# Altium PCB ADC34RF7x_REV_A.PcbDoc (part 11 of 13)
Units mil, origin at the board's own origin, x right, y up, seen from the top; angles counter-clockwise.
Board outline 6250 x 2716.54 mil, 18 copper layers (Top Layer, L2 GND, L3 PWR, L4 GND, L5 PWR/SIG, L6 GND, L7 SIGNAL, L8 GND, L9 GND, L10 SIGNAL, L11 GND, L12 SIGNAL, L13 GND, L14 PWR, L15 GND, L16 PWR/SIG, L16 GND, Bottom Layer), stack 95.314 mil thick; 668 components, 786 nets, 3150 pads, 2020 vias.
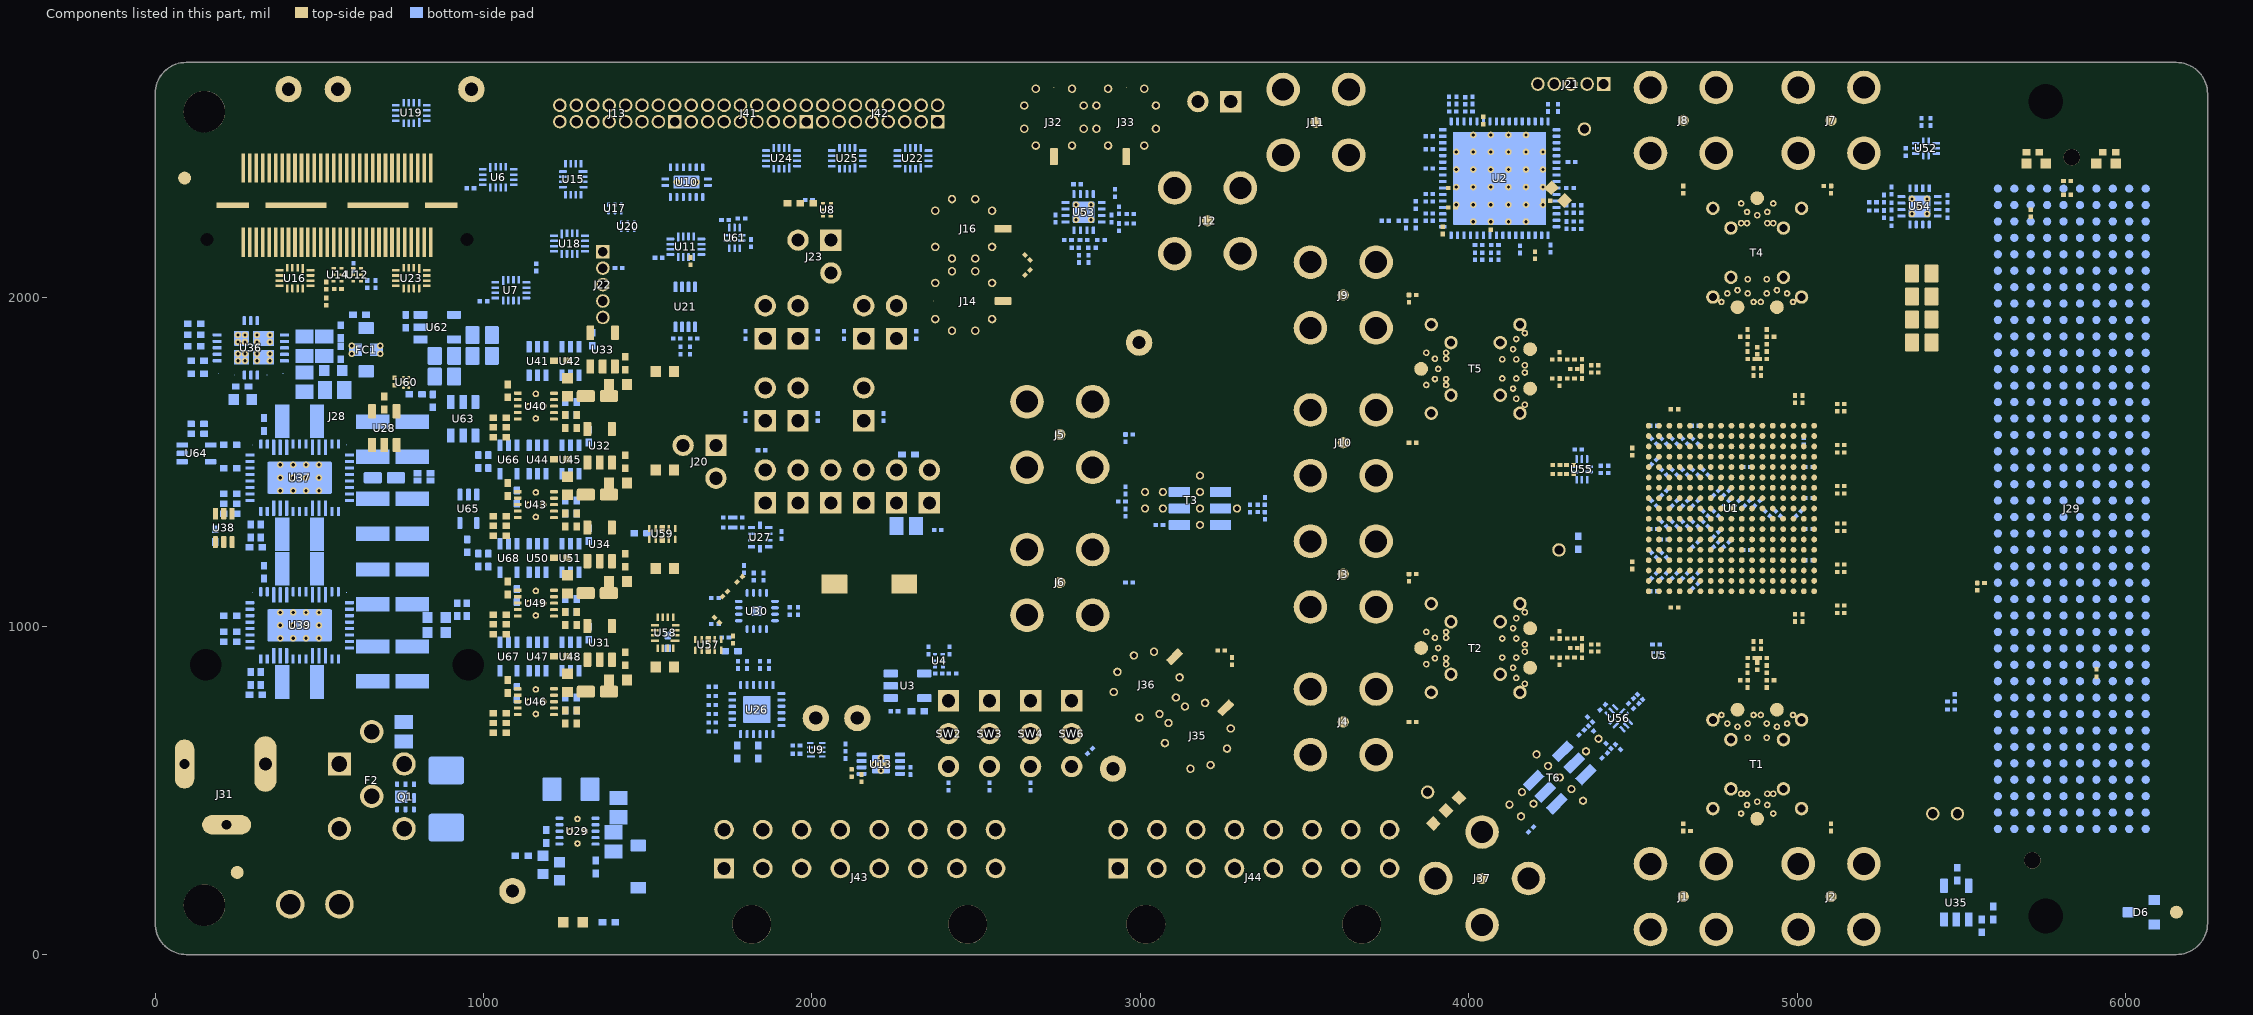
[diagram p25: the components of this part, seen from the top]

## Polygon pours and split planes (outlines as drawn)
GND on L7 SIGNAL "L2_GND" (solid, remove dead copper, pour order 106): 0,2716.54 0,0 6250,0 6250,2716.54
3p3V_Utility on L7 SIGNAL "L7_3p3V_Utility" (solid, remove dead copper, pour order 61): 4685.56,224.22 5983.78,224.22 6054.93,153.07 6054.93,11.36 6169.15,11.36 6169.15,623.31 5056.51,623.31 4713.3,966.52 4113.91,966.52 4113.91,1358.27 4366.11,1358.27 4366.11,1570.02 3974.52,1570.02 3974.52,939.64 2424.45,939.64 2424.45,1416.58 1599.5,1416.58 1599.5,1625.36 2405,1625.36 2405,2122.59 2864.77,2122.59 2864.77,2211.87 3798.01,2211.87 3798.01,2085.43 4310.89,2085.43 4310.89,2211.87 5403,2211.87 5403,2716.54 0,2716.54 0,516 4393.77,516
2p3V on L7 SIGNAL "L10_2p3V" (solid, remove dead copper, pour order 53): 860.85,756.43 1100.6,756.43 1100.6,1735.95 860.85,1735.95
GPIOVDD on L7 SIGNAL "L7 SIGNAL-GPIOVDD" (solid, remove dead copper, pour order 63): 4367.48,1452.76 4768.5,1452.76 4768.5,1515.75 4705.39,1515.75 4705.39,1544.15 4705.51,1544.15 4705.51,1965.61 2512.06,1965.61 2512.06,1625.36 1599.5,1625.36 1599.5,1415.24 3404.14,1415.24 3404.14,1570.26 4367.48,1570.26
3p3V_EEPROM on L7 SIGNAL "L7_SIGNAL_3P3V_EEPROM_P055" (solid, remove dead copper, pour order 55): 6054.93,5 6054.93,145.53 5976.25,224.22 2441.13,224.22 2441.13,616.15 2060.22,616.15 2060.22,5
ADC_VCM on L7 SIGNAL "L7 SIGNAL-ADC_VCM" (solid, remove dead copper, pour order 104): 4190,1160 4640,1160 4640,1450.51 4504.04,1450.51 4504.04,1306.82 4190,1306.82
DVDD09 on L3 PWR "L3_DVDD09" (solid, remove dead copper, pour order 96): 6250,1875.36 6250,565.81 690,565.81 690,1875.36
GPIOVADJ on L3 PWR "L3 PWR-GPIOVADJ" (solid, remove dead copper, pour order 59): 0,0 3936.19,0 3936.19,565.81 690,565.81 690,1890.01 1541.57,1890.01 1541.57,1802.11 1681.09,1802.11 1681.09,1890.01 1789.83,1890.01 1789.83,2371.77 2346.25,2371.77 2346.25,2715 0,2715
GND on L3 PWR "L2_GND" (solid, remove dead copper, pour order 110): 0,2716.54 0,0 6250,0 6250,2716.54
DVDDMEM09 on L3 PWR "L3_PWR_DVDDMEM09_P082" (solid, remove dead copper, pour order 82): 2338.72,1422.46 2157.76,1422.46 2157.76,1875.36 2589,1875.36 2589,2202.17 4768.5,2202.17 4768.5,1438.75 4674.02,1438.75 4674.02,1875.36 2754.08,1875.36 2754.08,1725.36 2339.5,1725.36
VADJ on L3 PWR "L3 PWR-VADJ" (solid, remove dead copper, pour order 99): 3936.19,0 6250,0 6250,550.52 3936.19,550.52
GND on Bottom Layer "L2_GND" (solid, remove dead copper, pour order 111): 0,2716.54 0,0 6250,0 6250,2716.54
NetC74_2 on Bottom Layer "FAN_PWR_BOTTOM" (solid, remove dead copper, pour order 79): 5522.4,496.98 5461.49,496.98 ccw(c5461.48,475.31) 5446.16,490.63 ccw(c5469.48,467.31) 5436.49,467.31 5436.49,381.67 ccw(c5469.19,381.67) 5446.07,358.55 cw(c5406.6,319.08) 5462.42,319.08 5462.42,198.63 ccw(c5474,198.63) 5474,187.05 5528.04,187.05 ccw(c5528.04,193.23) 5534.21,193.23 5534.21,485.24 ccw(c5522.46,485.24)
AVDD18 on L14 PWR "L14 PWR-AVDD18" (solid, remove dead copper, pour order 108): 1411.26,417 5203.52,417 5203.52,1902.33 1086.77,1902.33 1086.77,417
CLKVDD18 on L14 PWR "L5 PWR-CLKVDD18" (solid, remove dead copper, pour order 18): 1411.26,1035 2655,1035 4436.74,1035 4436.74,1263.78 4642.52,1263.78 4642.52,1421.26 2305.95,1421.26 2305.95,1263.78 1411.26,1263.78
GND on L14 PWR "L2_GND" (solid, remove dead copper, pour order 112): 0,2716.54 0,0 6250,0 6250,2716.54
12V on L14 PWR "L14 PWR-12V" (solid, remove dead copper, pour order 16): 0,-4 6250,-4 6250,335.95 622.67,335.95 622.67,1687.4 871.42,1687.4 871.42,2072 0,2072
GND on L14 PWR "L14_PWR_GND_P076" (solid, remove dead copper, pour order 76): 4436.74,1263.78 4548.03,1263.78 4548.03,746.01 2339.4,746.01 2339.4,912.44 1311.5,912.44 1311.5,1400.51 1775.05,1400.51 1775.05,1484.25 4548.03,1484.25 4548.03,1443.21 4642.52,1443.21 4642.52,1421.26 2305.95,1421.26 2305.95,1263.78 1411.26,1263.78 1411.26,1038.38 4436.74,1038.38
CLKVDD12 on L5 PWR/SIG "L5_CLKVDD12" (solid, remove dead copper, pour order 90): 1378.86,1152.68 4470.66,1152.68 4470.66,1240.99 4611.02,1240.99 4611.02,1389.76 1542.49,1389.76 1542.49,1462.43 1503.28,1501.65 1378.86,1501.65 1378.86,1389.76
GND on L5 PWR/SIG "L2_GND" (solid, remove dead copper, pour order 103): 0,2716.54 0,0 6250,0 6250,2716.54
AVDD12 on L5 PWR/SIG "L14_AVDD12" (solid, remove dead copper, pour order 102): 1575.37,1582.75 1575.36,1678.95 1378.59,1678.8 1379,1873.41 5730,1873.41 5730,715 4579.53,715 4579.53,1232.28 4611.02,1232.28 4611.02,1484.25 4511.41,1484.25 4511.41,1502.19 1655.93,1502.19
3p3V_AUX on L5 PWR/SIG "L5_PWR/SIG_3P3V_AUX_P009" (solid, remove dead copper, pour order 9): 5881.72,804.99 6135,804.99 6135,59.32 5881.72,59.32
VADJ on L5 PWR/SIG "L5_PWR/SIG_VADJ_P067" (solid, remove dead copper, pour order 67): 2758.55,805.03 3746.67,805.03 4022.7,529 4022.7,444.38 2919.21,444.38 2758.55,605.03
GND on L10 SIGNAL "L2_GND" (solid, remove dead copper, pour order 101): 0,2716.54 0,0 6250,0 6250,2716.54
GPIOVDD on L10 SIGNAL "L10 SIGNAL-GPIOVDD" (solid, remove dead copper, pour order 72): 2397.7,818.17 3119.66,818.17 3119.66,0 3978,0 3978,553 3553.43,553 3118.3,988.12 3118.3,1293.36 2502,1293.36 1775.05,1293.36 1775.05,2186.87 2541.03,2186.87 2541.03,2720 690,2720 690,1826.18 1514.84,1826.18 1514.84,1073.28 2240,1073.28 2240,818.17
DVDD09_uFit on L10 SIGNAL "L7_ADC_VCM" (solid, remove dead copper, pour order 60): 2151.24,338.02 2151.24,0 0,0 0,1630.43 994,1630.43 994,338.02
AVDD18_uFit on L10 SIGNAL "L7_ADC_VCM" (solid, remove dead copper, pour order 40): 3119.66,0 2382.49,0 2382.49,450 1510.79,450 1510.79,905.95 1900.5,905.95 1900.5,777.5 3119.66,777.5
DVDD09 on L10 SIGNAL "L10_SIGNAL_DVDD09_P057" (solid, remove dead copper, pour order 57): 860.43,1367.6 760.27,1367.6 760.27,1534.87 882.76,1534.87 882.76,1367.42
NetC63_2 on L10 SIGNAL "L10_SIGNAL_NETC63_2_P041" (solid, remove dead copper, pour order 41): 5246.71,2332.27 5246.71,2234.92 ccw(c5254.47,2234.92) 5254.47,2227.16 5264.3,2227.16 ccw(c5264.3,2236.81) 5273.95,2236.81 5273.95,2331.31 ccw(c5266.71,2331.31) 5266.71,2338.55 5252.99,2338.55 ccw(c5252.99,2332.27)
GND on L12 SIGNAL "L2_GND" (solid, remove dead copper, pour order 74): 0,2716.54 0,0 6250,0 6250,2716.54
GND on L12 SIGNAL "L12 SIGNAL-GND" (solid, remove dead copper, pour order 49): 4004.63,0 4171.11,0 4171.11,1513.48 1871.81,1513.48 1871.81,2076.86 471.01,2076.86 0,2078.26 0,0 2666.05,0 2666.05,510.34 1101.91,510.34 1101.91,1550.47 1775.05,1550.47 1775.05,1347.21 1321.5,1347.21 1321.5,645.83 3480,645.83 3480,0 3575.63,0 3575.63,794.85 1477.62,794.85 1477.62,1240.47 4004.63,1240.47
AVDD12_uFit on L12 SIGNAL "L7_ADC_VCM" (solid, remove dead copper, pour order 42): 2559.24,300.1 2559.24,0 622.67,0 622.67,1990.01 1723.03,1990.01 1723.03,1644.8 960,1644.8 960,300.1
CLKVDD12_uFit on L12 SIGNAL "L12_SIGNAL_CLKVDD12_UFIT_P044" (solid, remove dead copper, pour order 44): 3480,0 2666.05,0 2666.05,510.34 1101.87,510.34 1101.87,1552.46 1775.05,1552.46 1775.05,1347.21 1321.5,1347.21 1321.5,645.83 3480,645.83 3480,376.12
CLKVDD18_uFit on L12 SIGNAL "L12_SIGNAL_CLKVDD18_UFIT_P047" (solid, remove dead copper, pour order 47): 3575.63,0 3575.63,794.85 1478.42,794.85 1474.99,798.28 1477.62,800.91 1477.62,1240.47 4006.62,1240.47 4006.62,0
GND on L2 GND "L2_GND" (solid, remove dead copper, pour order 0): 0,2716.54 0,0 6250,0 6250,2716.54
GND on L4 GND "L2_GND" (solid, remove dead copper, pour order 58): 0,2716.54 0,0 6250,0 6250,2716.54
GND on L16 GND "L2_GND" (solid, remove dead copper, pour order 66): 0,2716.54 0,0 6250,0 6250,2716.54
GND on L6 GND "L2_GND" (solid, remove dead copper, pour order 69): 0,2716.54 0,0 6250,0 6250,2716.54
GND on L8 GND "L2_GND" (solid, remove dead copper, pour order 70): 0,2716.54 0,0 6250,0 6250,2716.54
GND on L9 GND "L2_GND" (solid, remove dead copper, pour order 71): 0,2716.54 0,0 6250,0 6250,2716.54
GND on L11 GND "L2_GND" (solid, remove dead copper, pour order 73): 0,2716.54 0,0 6250,0 6250,2716.54
GND on L13 GND "L2_GND" (solid, remove dead copper, pour order 75): 3.9,2716.54 3.9,0 6253.9,0 6253.9,2716.54
GND on L15 GND "L2_GND" (solid, remove dead copper, pour order 77): 0,2716.54 0,0 6250,0 6250,2716.54
GND on Top Layer "L2_GND" (solid, remove dead copper, pour order 87): 0,2716.54 0,0 6250,0 6250,2716.54
GND on L16 PWR/SIG "L2_GND" (solid, remove dead copper, pour order 78): 0,2716.54 0,0 6250,0 6250,2716.54

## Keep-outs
Keep-Out Layer:
  text ".Layer_Name" at 577,-858.49 h60

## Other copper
Top Layer:
  drawing of 117 lines, arcs and shapes, not listed
  text ".Layer_Name" at 577,-858.49 h60
L2 GND:
  pour cut-out: 4848.54,2303.16 ccw(c4878.54,2303.16) 4878.54,2273.16 ccw(c4878.54,2303.16) 4908.54,2303.16 ccw(c4878.54,2303.16) 4878.54,2333.16 ccw(c4878.54,2303.16)
  pour cut-out: 4788.54,1971.16 ccw(c4818.54,1971.16) 4818.54,1941.16 ccw(c4818.54,1971.16) 4848.54,1971.16 ccw(c4818.54,1971.16) 4818.54,2001.16 ccw(c4818.54,1971.16)
  pour cut-out: 4908.54,1971.16 ccw(c4938.54,1971.16) 4938.54,1941.16 ccw(c4938.54,1971.16) 4968.54,1971.16 ccw(c4938.54,1971.16) 4938.54,2001.16 ccw(c4938.54,1971.16)
  pour cut-out: 4157.11,1723.27 ccw(c4187.11,1723.27) 4187.11,1693.27 ccw(c4187.11,1723.27) 4217.11,1723.27 ccw(c4187.11,1723.27) 4187.11,1753.27 ccw(c4187.11,1723.27)
  pour cut-out: 4157.11,1843.27 ccw(c4187.11,1843.27) 4187.11,1813.27 ccw(c4187.11,1843.27) 4217.11,1843.27 ccw(c4187.11,1843.27) 4187.11,1873.27 ccw(c4187.11,1843.27)
  pour cut-out: 3825.11,1783.27 ccw(c3855.11,1783.27) 3855.11,1753.27 ccw(c3855.11,1783.27) 3885.11,1783.27 ccw(c3855.11,1783.27) 3855.11,1813.27 ccw(c3855.11,1783.27)
  pour cut-out: 4157.11,993.29 ccw(c4187.11,993.29) 4187.11,963.29 ccw(c4187.11,993.29) 4217.11,993.29 ccw(c4187.11,993.29) 4187.11,1023.29 ccw(c4187.11,993.29)
  pour cut-out: 4157.11,873.29 ccw(c4187.11,873.29) 4187.11,843.29 ccw(c4187.11,873.29) 4217.11,873.29 ccw(c4187.11,873.29) 4187.11,903.29 ccw(c4187.11,873.29)
  pour cut-out: 3825.11,933.29 ccw(c3855.11,933.29) 3855.11,903.29 ccw(c3855.11,933.29) 3885.11,933.29 ccw(c3855.11,933.29) 3855.11,963.29 ccw(c3855.11,933.29)
  pour cut-out: 4788.52,745.38 ccw(c4818.52,745.38) 4818.52,715.38 ccw(c4818.52,745.38) 4848.52,745.38 ccw(c4818.52,745.38) 4818.52,775.38 ccw(c4818.52,745.38)
  pour cut-out: 4908.52,745.38 ccw(c4938.52,745.38) 4938.52,715.38 ccw(c4938.52,745.38) 4968.52,745.38 ccw(c4938.52,745.38) 4938.52,775.38 ccw(c4938.52,745.38)
  pour cut-out: 4848.52,413.38 ccw(c4878.52,413.38) 4878.52,383.38 ccw(c4878.52,413.38) 4908.52,413.38 ccw(c4878.52,413.38) 4878.52,443.38 ccw(c4878.52,413.38)
  pour cut-out: 5073.54,2540.21 ccw(c5103.54,2540.21) 5103.54,2510.21 ccw(c5103.54,2540.21) 5133.54,2540.21 ccw(c5103.54,2540.21) 5103.54,2570.21 ccw(c5103.54,2540.21)
  pour cut-out: 4623.54,2540.21 ccw(c4653.54,2540.21) 4653.54,2510.21 ccw(c4653.54,2540.21) 4683.54,2540.21 ccw(c4653.54,2540.21) 4653.54,2570.21 ccw(c4653.54,2540.21)
  pour cut-out: 3588.06,2008.27 ccw(c3618.06,2008.27) 3618.06,1978.27 ccw(c3618.06,2008.27) 3648.06,2008.27 ccw(c3618.06,2008.27) 3618.06,2038.27 ccw(c3618.06,2008.27)
  pour cut-out: 3588.06,1558.27 ccw(c3618.06,1558.27) 3618.06,1528.27 ccw(c3618.06,1558.27) 3648.06,1558.27 ccw(c3618.06,1558.27) 3618.06,1588.27 ccw(c3618.06,1558.27)
  pour cut-out: 3588.06,1158.29 ccw(c3618.06,1158.29) 3618.06,1128.29 ccw(c3618.06,1158.29) 3648.06,1158.29 ccw(c3618.06,1158.29) 3618.06,1188.29 ccw(c3618.06,1158.29)
  pour cut-out: 3588.06,708.29 ccw(c3618.06,708.29) 3618.06,678.29 ccw(c3618.06,708.29) 3648.06,708.29 ccw(c3618.06,708.29) 3618.06,738.29 ccw(c3618.06,708.29)
  pour cut-out: 4623.52,176.33 ccw(c4653.52,176.33) 4653.52,146.33 ccw(c4653.52,176.33) 4683.52,176.33 ccw(c4653.52,176.33) 4653.52,206.33 ccw(c4653.52,176.33)
  pour cut-out: 5073.52,176.33 ccw(c5103.52,176.33) 5103.52,146.33 ccw(c5103.52,176.33) 5133.52,176.33 ccw(c5103.52,176.33) 5103.52,206.33 ccw(c5103.52,176.33)
  text ".Layer_Name" at 575.43,-860 h60
L3 PWR:
  pour cut-out: 4848.54,2303.16 ccw(c4878.54,2303.16) 4878.54,2273.16 ccw(c4878.54,2303.16) 4908.54,2303.16 ccw(c4878.54,2303.16) 4878.54,2333.16 ccw(c4878.54,2303.16)
  pour cut-out: 4788.54,1971.16 ccw(c4818.54,1971.16) 4818.54,1941.16 ccw(c4818.54,1971.16) 4848.54,1971.16 ccw(c4818.54,1971.16) 4818.54,2001.16 ccw(c4818.54,1971.16)
  pour cut-out: 4908.54,1971.16 ccw(c4938.54,1971.16) 4938.54,1941.16 ccw(c4938.54,1971.16) 4968.54,1971.16 ccw(c4938.54,1971.16) 4938.54,2001.16 ccw(c4938.54,1971.16)
  pour cut-out: 4157.11,1723.27 ccw(c4187.11,1723.27) 4187.11,1693.27 ccw(c4187.11,1723.27) 4217.11,1723.27 ccw(c4187.11,1723.27) 4187.11,1753.27 ccw(c4187.11,1723.27)
  pour cut-out: 4157.11,1843.27 ccw(c4187.11,1843.27) 4187.11,1813.27 ccw(c4187.11,1843.27) 4217.11,1843.27 ccw(c4187.11,1843.27) 4187.11,1873.27 ccw(c4187.11,1843.27)
  pour cut-out: 3825.11,1783.27 ccw(c3855.11,1783.27) 3855.11,1753.27 ccw(c3855.11,1783.27) 3885.11,1783.27 ccw(c3855.11,1783.27) 3855.11,1813.27 ccw(c3855.11,1783.27)
  pour cut-out: 4157.11,993.29 ccw(c4187.11,993.29) 4187.11,963.29 ccw(c4187.11,993.29) 4217.11,993.29 ccw(c4187.11,993.29) 4187.11,1023.29 ccw(c4187.11,993.29)
  pour cut-out: 4157.11,873.29 ccw(c4187.11,873.29) 4187.11,843.29 ccw(c4187.11,873.29) 4217.11,873.29 ccw(c4187.11,873.29) 4187.11,903.29 ccw(c4187.11,873.29)
  pour cut-out: 3825.11,933.29 ccw(c3855.11,933.29) 3855.11,903.29 ccw(c3855.11,933.29) 3885.11,933.29 ccw(c3855.11,933.29) 3855.11,963.29 ccw(c3855.11,933.29)
  pour cut-out: 4788.52,745.38 ccw(c4818.52,745.38) 4818.52,715.38 ccw(c4818.52,745.38) 4848.52,745.38 ccw(c4818.52,745.38) 4818.52,775.38 ccw(c4818.52,745.38)
  pour cut-out: 4908.52,745.38 ccw(c4938.52,745.38) 4938.52,715.38 ccw(c4938.52,745.38) 4968.52,745.38 ccw(c4938.52,745.38) 4938.52,775.38 ccw(c4938.52,745.38)
  pour cut-out: 4848.52,413.38 ccw(c4878.52,413.38) 4878.52,383.38 ccw(c4878.52,413.38) 4908.52,413.38 ccw(c4878.52,413.38) 4878.52,443.38 ccw(c4878.52,413.38)
  pour cut-out: 5073.54,2540.21 ccw(c5103.54,2540.21) 5103.54,2510.21 ccw(c5103.54,2540.21) 5133.54,2540.21 ccw(c5103.54,2540.21) 5103.54,2570.21 ccw(c5103.54,2540.21)
  pour cut-out: 4623.54,2540.21 ccw(c4653.54,2540.21) 4653.54,2510.21 ccw(c4653.54,2540.21) 4683.54,2540.21 ccw(c4653.54,2540.21) 4653.54,2570.21 ccw(c4653.54,2540.21)
  pour cut-out: 3588.06,2008.27 ccw(c3618.06,2008.27) 3618.06,1978.27 ccw(c3618.06,2008.27) 3648.06,2008.27 ccw(c3618.06,2008.27) 3618.06,2038.27 ccw(c3618.06,2008.27)
  pour cut-out: 3588.06,1558.27 ccw(c3618.06,1558.27) 3618.06,1528.27 ccw(c3618.06,1558.27) 3648.06,1558.27 ccw(c3618.06,1558.27) 3618.06,1588.27 ccw(c3618.06,1558.27)
  pour cut-out: 3588.06,1158.29 ccw(c3618.06,1158.29) 3618.06,1128.29 ccw(c3618.06,1158.29) 3648.06,1158.29 ccw(c3618.06,1158.29) 3618.06,1188.29 ccw(c3618.06,1158.29)
  pour cut-out: 3588.06,708.29 ccw(c3618.06,708.29) 3618.06,678.29 ccw(c3618.06,708.29) 3648.06,708.29 ccw(c3618.06,708.29) 3618.06,738.29 ccw(c3618.06,708.29)
  pour cut-out: 4623.52,176.33 ccw(c4653.52,176.33) 4653.52,146.33 ccw(c4653.52,176.33) 4683.52,176.33 ccw(c4653.52,176.33) 4653.52,206.33 ccw(c4653.52,176.33)
  pour cut-out: 5073.52,176.33 ccw(c5103.52,176.33) 5103.52,146.33 ccw(c5103.52,176.33) 5133.52,176.33 ccw(c5103.52,176.33) 5103.52,206.33 ccw(c5103.52,176.33)
  text ".Layer_Name" at 580,-860 h60
L4 GND:
  text ".Layer_Name" at 575.43,-860 h60
L15 GND:
  text ".Layer_Name" at 575,-860 h60
L16 PWR/SIG:
  pour cut-out: 1556.46,960.72 cw(c1556.46,971.72) 1545.46,971.72 cw(c1556.46,971.72) 1556.46,982.72 cw(c1556.46,971.72) 1567.46,971.72 cw(c1556.46,971.72)
  pour cut-out: 1790.56,1235.38 cw(c1790.56,1246.38) 1779.56,1246.38 cw(c1790.56,1246.38) 1790.56,1257.38 cw(c1790.56,1246.38) 1801.56,1246.38 cw(c1790.56,1246.38)
  pour cut-out: 3578.15,2634.21 ccw(c3634.82,2634.21) 3634.82,2577.54 ccw(c3634.82,2634.21) 3691.48,2634.21 ccw(c3634.82,2634.21) 3634.82,2690.87 ccw(c3634.82,2634.21)
  pour cut-out: 3378.15,2634.21 ccw(c3434.82,2634.21) 3434.82,2577.54 ccw(c3434.82,2634.21) 3491.48,2634.21 ccw(c3434.82,2634.21) 3434.82,2690.87 ccw(c3434.82,2634.21)
  pour cut-out: 4990.49,2002.16 ccw(c5013.54,2002.16) 5013.54,1979.11 ccw(c5013.54,2002.16) 5036.59,2002.16 ccw(c5013.54,2002.16) 5013.54,2025.21 ccw(c5013.54,2002.16)
  pour cut-out: 4935.49,2062.16 ccw(c4958.54,2062.16) 4958.54,2039.11 ccw(c4958.54,2062.16) 4981.59,2062.16 ccw(c4958.54,2062.16) 4958.54,2085.21 ccw(c4958.54,2062.16)
  pour cut-out: 4775.49,2062.16 ccw(c4798.54,2062.16) 4798.54,2039.11 ccw(c4798.54,2062.16) 4821.59,2062.16 ccw(c4798.54,2062.16) 4798.54,2085.21 ccw(c4798.54,2062.16)
  pour cut-out: 4938.54,2012.16 cw(c4938.54,2023.16) 4927.54,2023.16 cw(c4938.54,2023.16) 4938.54,2034.16 cw(c4938.54,2023.16) 4949.54,2023.16 cw(c4938.54,2023.16)
  pour cut-out: 4818.54,2012.16 cw(c4818.54,2023.16) 4807.54,2023.16 cw(c4818.54,2023.16) 4818.54,2034.16 cw(c4818.54,2023.16) 4829.54,2023.16 cw(c4818.54,2023.16)
  pour cut-out: 4171.11,1783.27 cw(c4171.11,1794.27) 4160.11,1794.27 cw(c4171.11,1794.27) 4171.11,1805.27 cw(c4171.11,1794.27) 4182.11,1794.27 cw(c4171.11,1794.27)
  pour cut-out: 4133.06,1918.27 ccw(c4156.11,1918.27) 4156.11,1895.22 ccw(c4156.11,1918.27) 4179.16,1918.27 ccw(c4156.11,1918.27) 4156.11,1941.32 ccw(c4156.11,1918.27)
  pour cut-out: 4133.06,1648.27 ccw(c4156.11,1648.27) 4156.11,1625.22 ccw(c4156.11,1648.27) 4179.16,1648.27 ccw(c4156.11,1648.27) 4156.11,1671.32 ccw(c4156.11,1648.27)
  pour cut-out: 3058.88,643.76 ccw(c3074.78,643.76) 3074.78,627.86 ccw(c3074.78,643.76) 3090.68,643.76 ccw(c3074.78,643.76) 3074.78,659.66 ccw(c3074.78,643.76)
  pour cut-out: 2964.56,910.68 ccw(c2980.46,910.68) 2980.46,894.78 ccw(c2980.46,910.68) 2996.36,910.68 ccw(c2980.46,910.68) 2980.46,926.58 ccw(c2980.46,910.68)
  pour cut-out: 2914.45,860.57 ccw(c2930.35,860.57) 2930.35,844.67 ccw(c2930.35,860.57) 2946.25,860.57 ccw(c2930.35,860.57) 2930.35,876.47 ccw(c2930.35,860.57)
  pour cut-out: 4135.11,862.29 cw(c4135.11,873.29) 4124.11,873.29 cw(c4135.11,873.29) 4135.11,884.29 cw(c4135.11,873.29) 4146.11,873.29 cw(c4135.11,873.29)
  pour cut-out: 3931.11,891.29 cw(c3931.11,902.29) 3920.11,902.29 cw(c3931.11,902.29) 3931.11,913.29 cw(c3931.11,902.29) 3942.11,902.29 cw(c3931.11,902.29)
  pour cut-out: 3897.11,891.29 cw(c3897.11,902.29) 3886.11,902.29 cw(c3897.11,902.29) 3897.11,913.29 cw(c3897.11,902.29) 3908.11,902.29 cw(c3897.11,902.29)
  pour cut-out: 4171.11,1031.29 cw(c4171.11,1042.29) 4160.11,1042.29 cw(c4171.11,1042.29) 4171.11,1053.29 cw(c4171.11,1042.29) 4182.11,1042.29 cw(c4171.11,1042.29)
  pour cut-out: 4171.11,911.29 cw(c4171.11,922.29) 4160.11,922.29 cw(c4171.11,922.29) 4171.11,933.29 cw(c4171.11,922.29) 4182.11,922.29 cw(c4171.11,922.29)
  pour cut-out: 4145.11,951.29 cw(c4145.11,962.29) 4134.11,962.29 cw(c4145.11,962.29) 4145.11,973.29 cw(c4145.11,962.29) 4156.11,962.29 cw(c4145.11,962.29)
  pour cut-out: 4102.11,951.29 cw(c4102.11,962.29) 4091.11,962.29 cw(c4102.11,962.29) 4102.11,973.29 cw(c4102.11,962.29) 4113.11,962.29 cw(c4102.11,962.29)
  pour cut-out: 3897.11,953.29 cw(c3897.11,964.29) 3886.11,964.29 cw(c3897.11,964.29) 3897.11,975.29 cw(c3897.11,964.29) 3908.11,964.29 cw(c3897.11,964.29)
  pour cut-out: 3931.11,953.29 cw(c3931.11,964.29) 3920.11,964.29 cw(c3931.11,964.29) 3931.11,975.29 cw(c3931.11,964.29) 3942.11,964.29 cw(c3931.11,964.29)
  pour cut-out: 4174.5,2220.77 cw(c4174.5,2231.77) 4163.5,2231.77 cw(c4174.5,2231.77) 4174.5,2242.77 cw(c4174.5,2231.77) 4185.5,2231.77 cw(c4174.5,2231.77)
  pour cut-out: 4120.96,2220.77 cw(c4120.96,2231.77) 4109.96,2231.77 cw(c4120.96,2231.77) 4120.96,2242.77 cw(c4120.96,2231.77) 4131.96,2231.77 cw(c4120.96,2231.77)
  pour cut-out: 4067.42,2220.77 cw(c4067.42,2231.77) 4056.42,2231.77 cw(c4067.42,2231.77) 4067.42,2242.77 cw(c4067.42,2231.77) 4078.42,2231.77 cw(c4067.42,2231.77)
  pour cut-out: 4013.87,2272.34 cw(c4013.87,2283.34) 4002.87,2283.34 cw(c4013.87,2283.34) 4013.87,2294.34 cw(c4013.87,2283.34) 4024.87,2283.34 cw(c4013.87,2283.34)
  pour cut-out: 4013.87,2220.77 cw(c4013.87,2231.77) 4002.87,2231.77 cw(c4013.87,2231.77) 4013.87,2242.77 cw(c4013.87,2231.77) 4024.87,2231.77 cw(c4013.87,2231.77)
  pour cut-out: 3931.11,1803.27 cw(c3931.11,1814.27) 3920.11,1814.27 cw(c3931.11,1814.27) 3931.11,1825.27 cw(c3931.11,1814.27) 3942.11,1814.27 cw(c3931.11,1814.27)
  pour cut-out: 3931.11,1741.27 cw(c3931.11,1752.27) 3920.11,1752.27 cw(c3931.11,1752.27) 3931.11,1763.27 cw(c3931.11,1752.27) 3942.11,1752.27 cw(c3931.11,1752.27)
  pour cut-out: 3897.11,1741.27 cw(c3897.11,1752.27) 3886.11,1752.27 cw(c3897.11,1752.27) 3897.11,1763.27 cw(c3897.11,1752.27) 3908.11,1752.27 cw(c3897.11,1752.27)
  pour cut-out: 3897.11,1803.27 cw(c3897.11,1814.27) 3886.11,1814.27 cw(c3897.11,1814.27) 3897.11,1825.27 cw(c3897.11,1814.27) 3908.11,1814.27 cw(c3897.11,1814.27)
  pour cut-out: 4135.11,1832.27 cw(c4135.11,1843.27) 4124.11,1843.27 cw(c4135.11,1843.27) 4135.11,1854.27 cw(c4135.11,1843.27) 4146.11,1843.27 cw(c4135.11,1843.27)
  pour cut-out: 4145.07,1681.22 cw(c4145.07,1692.22) 4134.07,1692.22 cw(c4145.07,1692.22) 4145.07,1703.22 cw(c4145.07,1692.22) 4156.07,1692.22 cw(c4145.07,1692.22)
  pour cut-out: 4171.11,1663.27 cw(c4171.11,1674.27) 4160.11,1674.27 cw(c4171.11,1674.27) 4171.11,1685.27 cw(c4171.11,1674.27) 4182.11,1674.27 cw(c4171.11,1674.27)
  pour cut-out: 487.86,1130.25 cw(c487.86,1144.25) 473.86,1144.25 cw(c487.86,1144.25) 487.86,1158.25 cw(c487.86,1144.25) 501.86,1144.25 cw(c487.86,1144.25)
  pour cut-out: 487.86,785.21 cw(c487.86,799.21) 473.86,799.21 cw(c487.86,799.21) 487.86,813.21 cw(c487.86,799.21) 501.86,799.21 cw(c487.86,799.21)
  pour cut-out: 4957.48,1315.77 cw(c4957.48,1326.77) 4946.48,1326.77 cw(c4957.48,1326.77) 4957.48,1337.77 cw(c4957.48,1326.77) 4968.48,1326.77 cw(c4957.48,1326.77)
  pour cut-out: 4862.99,1347.27 cw(c4862.99,1358.27) 4851.99,1358.27 cw(c4862.99,1358.27) 4862.99,1369.27 cw(c4862.99,1358.27) 4873.99,1358.27 cw(c4862.99,1358.27)
  pour cut-out: 5051.97,1441.76 cw(c5051.97,1452.76) 5040.97,1452.76 cw(c5051.97,1452.76) 5051.97,1463.76 cw(c5051.97,1452.76) 5062.97,1452.76 cw(c5051.97,1452.76)
  pour cut-out: 4862.99,1473.25 cw(c4862.99,1484.25) 4851.99,1484.25 cw(c4862.99,1484.25) 4862.99,1495.25 cw(c4862.99,1484.25) 4873.99,1484.25 cw(c4862.99,1484.25)
  pour cut-out: 4862.99,1315.77 cw(c4862.99,1326.77) 4851.99,1326.77 cw(c4862.99,1326.77) 4862.99,1337.77 cw(c4862.99,1326.77) 4873.99,1326.77 cw(c4862.99,1326.77)
  pour cut-out: 4924.61,930.8 cw(c4924.61,941.8) 4913.61,941.8 cw(c4924.61,941.8) 4924.61,952.8 cw(c4924.61,941.8) 4935.61,941.8 cw(c4924.61,941.8)
  pour cut-out: 4957.48,1018.28 cw(c4957.48,1029.28) 4946.48,1029.28 cw(c4957.48,1029.28) 4957.48,1040.28 cw(c4957.48,1029.28) 4968.48,1029.28 cw(c4957.48,1029.28)
  pour cut-out: 4957.48,1095.3 cw(c4957.48,1106.3) 4946.48,1106.3 cw(c4957.48,1106.3) 4957.48,1117.3 cw(c4957.48,1106.3) 4968.48,1106.3 cw(c4957.48,1106.3)
  pour cut-out: 4238.83,231.61 ccw(c4182.17,231.61) 4182.17,288.28 ccw(c4182.17,231.61) 4125.5,231.61 ccw(c4182.17,231.61) 4182.17,174.95 ccw(c4182.17,231.61)
  pour cut-out: 3955.99,231.61 ccw(c3899.33,231.61) 3899.33,288.28 ccw(c3899.33,231.61) 3842.66,231.61 ccw(c3899.33,231.61) 3899.33,174.95 ccw(c3899.33,231.61)
  pour cut-out: 1800.78,735.01 cw(c1800.78,746.01) 1789.78,746.01 cw(c1800.78,746.01) 1800.78,757.01 cw(c1800.78,746.01) 1811.78,746.01 cw(c1800.78,746.01)
  pour cut-out: 487.86,845.21 cw(c487.86,859.21) 473.86,859.21 cw(c487.86,859.21) 487.86,873.21 cw(c487.86,859.21) 501.86,859.21 cw(c487.86,859.21)
  pour cut-out: 4548.03,1095.3 cw(c4548.03,1106.3) 4537.03,1106.3 cw(c4548.03,1106.3) 4548.03,1117.3 cw(c4548.03,1106.3) 4559.03,1106.3 cw(c4548.03,1106.3)
  pour cut-out: 4984.39,1902.37 cw(c4984.39,1913.37) 4973.39,1913.37 cw(c4984.39,1913.37) 4984.39,1924.37 cw(c4984.39,1913.37) 4995.39,1913.37 cw(c4984.39,1913.37)
  pour cut-out: 4806.43,1902.4 cw(c4806.43,1913.4) 4795.43,1913.4 cw(c4806.43,1913.4) 4806.43,1924.4 cw(c4806.43,1913.4) 4817.43,1913.4 cw(c4806.43,1913.4)
  pour cut-out: 4763.57,1902.37 cw(c4763.57,1913.37) 4752.57,1913.37 cw(c4763.57,1913.37) 4763.57,1924.37 cw(c4763.57,1913.37) 4774.57,1913.37 cw(c4763.57,1913.37)
  pour cut-out: 4097.41,373.03 ccw(c4040.75,373.03) 4040.75,429.7 ccw(c4040.75,373.03) 3984.08,373.03 ccw(c4040.75,373.03) 4040.75,316.37 ccw(c4040.75,373.03)
  pour cut-out: 3774.73,1058.29 ccw(c3718.06,1058.29) 3718.06,1114.96 ccw(c3718.06,1058.29) 3661.4,1058.29 ccw(c3718.06,1058.29) 3718.06,1001.62 ccw(c3718.06,1058.29)
  pour cut-out: 3574.73,1058.29 ccw(c3518.06,1058.29) 3518.06,1114.96 ccw(c3518.06,1058.29) 3461.4,1058.29 ccw(c3518.06,1058.29) 3518.06,1001.62 ccw(c3518.06,1058.29)
  pour cut-out: 3774.73,1258.29 ccw(c3718.06,1258.29) 3718.06,1314.96 ccw(c3718.06,1258.29) 3661.4,1258.29 ccw(c3718.06,1258.29) 3718.06,1201.62 ccw(c3718.06,1258.29)
  pour cut-out: 3574.73,1258.29 ccw(c3518.06,1258.29) 3518.06,1314.96 ccw(c3518.06,1258.29) 3461.4,1258.29 ccw(c3518.06,1258.29) 3518.06,1201.62 ccw(c3518.06,1258.29)
  pour cut-out: 2855,976.61 ccw(c2855,1033.28) 2911.67,1033.28 ccw(c2855,1033.28) 2855,1089.95 ccw(c2855,1033.28) 2798.33,1033.28 ccw(c2855,1033.28)
  pour cut-out: 2855,1176.61 ccw(c2855,1233.28) 2911.67,1233.28 ccw(c2855,1233.28) 2855,1289.95 ccw(c2855,1233.28) 2798.33,1233.28 ccw(c2855,1233.28)
  pour cut-out: 2855,1426.61 ccw(c2855,1483.28) 2911.67,1483.28 ccw(c2855,1483.28) 2855,1539.95 ccw(c2855,1483.28) 2798.33,1483.28 ccw(c2855,1483.28)
  pour cut-out: 2855,1626.61 ccw(c2855,1683.28) 2911.67,1683.28 ccw(c2855,1683.28) 2855,1739.95 ccw(c2855,1683.28) 2798.33,1683.28 ccw(c2855,1683.28)
  pour cut-out: 3461.4,1658.27 ccw(c3518.06,1658.27) 3518.06,1601.6 ccw(c3518.06,1658.27) 3574.73,1658.27 ccw(c3518.06,1658.27) 3518.06,1714.93 ccw(c3518.06,1658.27)
  pour cut-out: 3661.4,1658.27 ccw(c3718.06,1658.27) 3718.06,1601.6 ccw(c3718.06,1658.27) 3774.73,1658.27 ccw(c3718.06,1658.27) 3718.06,1714.93 ccw(c3718.06,1658.27)
  pour cut-out: 3461.4,1458.27 ccw(c3518.06,1458.27) 3518.06,1401.6 ccw(c3518.06,1458.27) 3574.73,1458.27 ccw(c3518.06,1458.27) 3518.06,1514.93 ccw(c3518.06,1458.27)
  pour cut-out: 3661.4,1458.27 ccw(c3718.06,1458.27) 3718.06,1401.6 ccw(c3718.06,1458.27) 3774.73,1458.27 ccw(c3718.06,1458.27) 3718.06,1514.93 ccw(c3718.06,1458.27)
  pour cut-out: 3461.4,1908.27 ccw(c3518.06,1908.27) 3518.06,1851.6 ccw(c3518.06,1908.27) 3574.73,1908.27 ccw(c3518.06,1908.27) 3518.06,1964.93 ccw(c3518.06,1908.27)
  pour cut-out: 3661.4,1908.27 ccw(c3718.06,1908.27) 3718.06,1851.6 ccw(c3718.06,1908.27) 3774.73,1908.27 ccw(c3718.06,1908.27) 3718.06,1964.93 ccw(c3718.06,1908.27)
  pour cut-out: 3461.4,2108.27 ccw(c3518.06,2108.27) 3518.06,2051.6 ccw(c3518.06,2108.27) 3574.73,2108.27 ccw(c3518.06,2108.27) 3518.06,2164.93 ccw(c3518.06,2108.27)
  pour cut-out: 3661.4,2108.27 ccw(c3718.06,2108.27) 3718.06,2051.6 ccw(c3718.06,2108.27) 3774.73,2108.27 ccw(c3718.06,2108.27) 3718.06,2164.93 ccw(c3718.06,2108.27)
  pour cut-out: 3048.15,2134.21 ccw(c3104.82,2134.21) 3104.82,2077.54 ccw(c3104.82,2134.21) 3161.48,2134.21 ccw(c3104.82,2134.21) 3104.82,2190.87 ccw(c3104.82,2134.21)
  pour cut-out: 3248.15,2134.21 ccw(c3304.82,2134.21) 3304.82,2077.54 ccw(c3304.82,2134.21) 3361.48,2134.21 ccw(c3304.82,2134.21) 3304.82,2190.87 ccw(c3304.82,2134.21)
  pour cut-out: 3048.15,2334.21 ccw(c3104.82,2334.21) 3104.82,2277.54 ccw(c3104.82,2334.21) 3161.48,2334.21 ccw(c3104.82,2334.21) 3104.82,2390.87 ccw(c3104.82,2334.21)
  pour cut-out: 3248.15,2334.21 ccw(c3304.82,2334.21) 3304.82,2277.54 ccw(c3304.82,2334.21) 3361.48,2334.21 ccw(c3304.82,2334.21) 3304.82,2390.87 ccw(c3304.82,2334.21)
  pour cut-out: 3378.15,2434.21 ccw(c3434.82,2434.21) 3434.82,2377.54 ccw(c3434.82,2434.21) 3491.48,2434.21 ccw(c3434.82,2434.21) 3434.82,2490.87 ccw(c3434.82,2434.21)
  pour cut-out: 3578.15,2434.21 ccw(c3634.82,2434.21) 3634.82,2377.54 ccw(c3634.82,2434.21) 3691.48,2434.21 ccw(c3634.82,2434.21) 3634.82,2490.87 ccw(c3634.82,2434.21)
  pour cut-out: 3660.49,1954.84 cw(c3660.49,1965.84) 3649.49,1965.84 cw(c3660.49,1965.84) 3660.49,1976.84 cw(c3660.49,1965.84) 3671.49,1965.84 cw(c3660.49,1965.84)
  pour cut-out: 3618.06,1937.27 cw(c3618.06,1948.27) 3607.06,1948.27 cw(c3618.06,1948.27) 3618.06,1959.27 cw(c3618.06,1948.27) 3629.06,1948.27 cw(c3618.06,1948.27)
  pour cut-out: 3618.06,2051.27 cw(c3618.06,2062.27) 3607.06,2062.27 cw(c3618.06,2062.27) 3618.06,2073.27 cw(c3618.06,2062.27) 3629.06,2062.27 cw(c3618.06,2062.27)
  pour cut-out: 3381.32,2191.17 cw(c3381.32,2202.17) 3370.32,2202.17 cw(c3381.32,2202.17) 3381.32,2213.17 cw(c3381.32,2202.17) 3392.32,2202.17 cw(c3381.32,2202.17)
  pour cut-out: 3461.32,2191.17 cw(c3461.32,2202.17) 3450.32,2202.17 cw(c3461.32,2202.17) 3461.32,2213.17 cw(c3461.32,2202.17) 3472.32,2202.17 cw(c3461.32,2202.17)
  pour cut-out: 3541.32,2191.17 cw(c3541.32,2202.17) 3530.32,2202.17 cw(c3541.32,2202.17) 3541.32,2213.17 cw(c3541.32,2202.17) 3552.32,2202.17 cw(c3541.32,2202.17)
  pour cut-out: 3621.32,2191.17 cw(c3621.32,2202.17) 3610.32,2202.17 cw(c3621.32,2202.17) 3621.32,2213.17 cw(c3621.32,2202.17) 3632.32,2202.17 cw(c3621.32,2202.17)
  pour cut-out: 3701.32,2191.17 cw(c3701.32,2202.17) 3690.32,2202.17 cw(c3701.32,2202.17) 3701.32,2213.17 cw(c3701.32,2202.17) 3712.32,2202.17 cw(c3701.32,2202.17)
  pour cut-out: 3838.93,2194.07 cw(c3838.93,2205.07) 3827.93,2205.07 cw(c3838.93,2205.07) 3838.93,2216.07 cw(c3838.93,2205.07) 3849.93,2205.07 cw(c3838.93,2205.07)
  pour cut-out: 3920.97,2175.89 cw(c3920.97,2186.89) 3909.97,2186.89 cw(c3920.97,2186.89) 3920.97,2197.89 cw(c3920.97,2186.89) 3931.97,2186.89 cw(c3920.97,2186.89)
  pour cut-out: 3904.79,2112.77 cw(c3904.79,2123.77) 3893.79,2123.77 cw(c3904.79,2123.77) 3904.79,2134.77 cw(c3904.79,2123.77) 3915.79,2123.77 cw(c3904.79,2123.77)
  pour cut-out: 3981.79,2112.77 cw(c3981.79,2123.77) 3970.79,2123.77 cw(c3981.79,2123.77) 3981.79,2134.77 cw(c3981.79,2123.77) 3992.79,2123.77 cw(c3981.79,2123.77)
  pour cut-out: 3786.02,1864.05 cw(c3786.02,1875.05) 3775.02,1875.05 cw(c3786.02,1875.05) 3786.02,1886.05 cw(c3786.02,1875.05) 3797.02,1875.05 cw(c3786.02,1875.05)
  pour cut-out: 3786.02,1944.05 cw(c3786.02,1955.05) 3775.02,1955.05 cw(c3786.02,1955.05) 3786.02,1966.05 cw(c3786.02,1955.05) 3797.02,1955.05 cw(c3786.02,1955.05)
  pour cut-out: 4328.98,1999.16 cw(c4328.98,2010.16) 4317.98,2010.16 cw(c4328.98,2010.16) 4328.98,2021.16 cw(c4328.98,2010.16) 4339.98,2010.16 cw(c4328.98,2010.16)
  pour cut-out: 3861.82,2245.88 cw(c3861.82,2256.88) 3850.82,2256.88 cw(c3861.82,2256.88) 3861.82,2267.88 cw(c3861.82,2256.88) 3872.82,2256.88 cw(c3861.82,2256.88)
  pour cut-out: 3889.35,2592.54 cw(c3889.35,2603.54) 3878.35,2603.54 cw(c3889.35,2603.54) 3889.35,2614.54 cw(c3889.35,2603.54) 3900.35,2603.54 cw(c3889.35,2603.54)
  pour cut-out: 5661.42,1821.27 cw(c5661.42,1832.27) 5650.42,1832.27 cw(c5661.42,1832.27) 5661.42,1843.27 cw(c5661.42,1832.27) 5672.42,1832.27 cw(c5661.42,1832.27)
  pour cut-out: 5711.42,1471.27 cw(c5711.42,1482.27) 5700.42,1482.27 cw(c5711.42,1482.27) 5711.42,1493.27 cw(c5711.42,1482.27) 5722.42,1482.27 cw(c5711.42,1482.27)
  pour cut-out: 5761.42,1521.27 cw(c5761.42,1532.27) 5750.42,1532.27 cw(c5761.42,1532.27) 5761.42,1543.27 cw(c5761.42,1532.27) 5772.42,1532.27 cw(c5761.42,1532.27)
  pour cut-out: 5861.42,1671.27 cw(c5861.42,1682.27) 5850.42,1682.27 cw(c5861.42,1682.27) 5861.42,1693.27 cw(c5861.42,1682.27) 5872.42,1682.27 cw(c5861.42,1682.27)
  pour cut-out: 5861.42,1521.27 cw(c5861.42,1532.27) 5850.42,1532.27 cw(c5861.42,1532.27) 5861.42,1543.27 cw(c5861.42,1532.27) 5872.42,1532.27 cw(c5861.42,1532.27)
  pour cut-out: 5861.42,1371.27 cw(c5861.42,1382.27) 5850.42,1382.27 cw(c5861.42,1382.27) 5861.42,1393.27 cw(c5861.42,1382.27) 5872.42,1382.27 cw(c5861.42,1382.27)
  pour cut-out: 5861.42,1221.27 cw(c5861.42,1232.27) 5850.42,1232.27 cw(c5861.42,1232.27) 5861.42,1243.27 cw(c5861.42,1232.27) 5872.42,1232.27 cw(c5861.42,1232.27)
  pour cut-out: 4779.8,760.11 cw(c4779.8,771.11) 4768.8,771.11 cw(c4779.8,771.11) 4779.8,782.11 cw(c4779.8,771.11) 4790.8,771.11 cw(c4779.8,771.11)
  pour cut-out: 4903.87,1005.96 cw(c4903.87,1016.96) 4892.87,1016.96 cw(c4903.87,1016.96) 4903.87,1027.96 cw(c4903.87,1016.96) 4914.87,1016.96 cw(c4903.87,1016.96)
  pour cut-out: 5051.97,1095.3 cw(c5051.97,1106.3) 5040.97,1106.3 cw(c5051.97,1106.3) 5051.97,1117.3 cw(c5051.97,1106.3) 5062.97,1106.3 cw(c5051.97,1106.3)
  pour cut-out: 5020.47,1126.8 cw(c5020.47,1137.8) 5009.47,1137.8 cw(c5020.47,1137.8) 5020.47,1148.8 cw(c5020.47,1137.8) 5031.47,1137.8 cw(c5020.47,1137.8)
  pour cut-out: 5051.97,1252.78 cw(c5051.97,1263.78) 5040.97,1263.78 cw(c5051.97,1263.78) 5051.97,1274.78 cw(c5051.97,1263.78) 5062.97,1263.78 cw(c5051.97,1263.78)
  pour cut-out: 4862.99,1221.28 cw(c4862.99,1232.28) 4851.99,1232.28 cw(c4862.99,1232.28) 4862.99,1243.28 cw(c4862.99,1232.28) 4873.99,1232.28 cw(c4862.99,1232.28)
  pour cut-out: 5051.97,1599.24 cw(c5051.97,1610.24) 5040.97,1610.24 cw(c5051.97,1610.24) 5051.97,1621.24 cw(c5051.97,1610.24) 5062.97,1610.24 cw(c5051.97,1610.24)
  pour cut-out: 4957.48,1599.24 cw(c4957.48,1610.24) 4946.48,1610.24 cw(c4957.48,1610.24) 4957.48,1621.24 cw(c4957.48,1610.24) 4968.48,1610.24 cw(c4957.48,1610.24)
  pour cut-out: 4203.21,1668.47 cw(c4203.21,1679.47) 4192.21,1679.47 cw(c4203.21,1679.47) 4203.21,1690.47 cw(c4203.21,1679.47) 4214.21,1679.47 cw(c4203.21,1679.47)
  pour cut-out: 4240.88,1696.41 cw(c4240.88,1707.41) 4229.88,1707.41 cw(c4240.88,1707.41) 4240.88,1718.41 cw(c4240.88,1707.41) 4251.88,1707.41 cw(c4240.88,1707.41)
  pour cut-out: 4308.98,1673.35 cw(c4308.98,1684.35) 4297.98,1684.35 cw(c4308.98,1684.35) 4308.98,1695.35 cw(c4308.98,1684.35) 4319.98,1684.35 cw(c4308.98,1684.35)
  pour cut-out: 4410.9,1659.74 cw(c4410.9,1670.74) 4399.9,1670.74 cw(c4410.9,1670.74) 4410.9,1681.74 cw(c4410.9,1670.74) 4421.9,1670.74 cw(c4410.9,1670.74)
  pour cut-out: 4482.29,1690.1 cw(c4482.29,1701.1) 4471.29,1701.1 cw(c4482.29,1701.1) 4482.29,1712.1 cw(c4482.29,1701.1) 4493.29,1701.1 cw(c4482.29,1701.1)
  pour cut-out: 4410.9,1579.74 cw(c4410.9,1590.74) 4399.9,1590.74 cw(c4410.9,1590.74) 4410.9,1601.74 cw(c4410.9,1590.74) 4421.9,1590.74 cw(c4410.9,1590.74)
  pour cut-out: 4166.62,1515.23 cw(c4166.62,1526.23) 4155.62,1526.23 cw(c4166.62,1526.23) 4166.62,1537.23 cw(c4166.62,1526.23) 4177.62,1526.23 cw(c4166.62,1526.23)
  pour cut-out: 4287.86,1504.74 cw(c4287.86,1515.74) 4276.86,1515.74 cw(c4287.86,1515.74) 4287.86,1526.74 cw(c4287.86,1515.74) 4298.86,1515.74 cw(c4287.86,1515.74)
  pour cut-out: 4579.53,1473.25 cw(c4579.53,1484.25) 4568.53,1484.25 cw(c4579.53,1484.25) 4579.53,1495.25 cw(c4579.53,1484.25) 4590.53,1484.25 cw(c4579.53,1484.25)
  pour cut-out: 4611.02,1473.25 cw(c4611.02,1484.25) 4600.02,1484.25 cw(c4611.02,1484.25) 4611.02,1495.25 cw(c4611.02,1484.25) 4622.02,1484.25 cw(c4611.02,1484.25)
  pour cut-out: 4642.52,1473.25 cw(c4642.52,1484.25) 4631.52,1484.25 cw(c4642.52,1484.25) 4642.52,1495.25 cw(c4642.52,1484.25) 4653.52,1484.25 cw(c4642.52,1484.25)
  pour cut-out: 4674.02,1473.25 cw(c4674.02,1484.25) 4663.02,1484.25 cw(c4674.02,1484.25) 4674.02,1495.25 cw(c4674.02,1484.25) 4685.02,1484.25 cw(c4674.02,1484.25)
  pour cut-out: 4705.51,1410.26 cw(c4705.51,1421.26) 4694.51,1421.26 cw(c4705.51,1421.26) 4705.51,1432.26 cw(c4705.51,1421.26) 4716.51,1421.26 cw(c4705.51,1421.26)
  pour cut-out: 4768.5,1347.27 cw(c4768.5,1358.27) 4757.5,1358.27 cw(c4768.5,1358.27) 4768.5,1369.27 cw(c4768.5,1358.27) 4779.5,1358.27 cw(c4768.5,1358.27)
  pour cut-out: 4768.5,1315.77 cw(c4768.5,1326.77) 4757.5,1326.77 cw(c4768.5,1326.77) 4768.5,1337.77 cw(c4768.5,1326.77) 4779.5,1326.77 cw(c4768.5,1326.77)
  pour cut-out: 4768.5,1284.28 cw(c4768.5,1295.28) 4757.5,1295.28 cw(c4768.5,1295.28) 4768.5,1306.28 cw(c4768.5,1295.28) 4779.5,1295.28 cw(c4768.5,1295.28)
  pour cut-out: 4768.5,1252.78 cw(c4768.5,1263.78) 4757.5,1263.78 cw(c4768.5,1263.78) 4768.5,1274.78 cw(c4768.5,1263.78) 4779.5,1263.78 cw(c4768.5,1263.78)
  pour cut-out: 4705.51,1126.8 cw(c4705.51,1137.8) 4694.51,1137.8 cw(c4705.51,1137.8) 4705.51,1148.8 cw(c4705.51,1137.8) 4716.51,1137.8 cw(c4705.51,1137.8)
  pour cut-out: 4674.02,1126.8 cw(c4674.02,1137.8) 4663.02,1137.8 cw(c4674.02,1137.8) 4674.02,1148.8 cw(c4674.02,1137.8) 4685.02,1137.8 cw(c4674.02,1137.8)
  pour cut-out: 4642.52,1126.8 cw(c4642.52,1137.8) 4631.52,1137.8 cw(c4642.52,1137.8) 4642.52,1148.8 cw(c4642.52,1137.8) 4653.52,1137.8 cw(c4642.52,1137.8)
  pour cut-out: 4611.02,1126.8 cw(c4611.02,1137.8) 4600.02,1137.8 cw(c4611.02,1137.8) 4611.02,1148.8 cw(c4611.02,1137.8) 4622.02,1137.8 cw(c4611.02,1137.8)
  pour cut-out: 4579.53,1126.8 cw(c4579.53,1137.8) 4568.53,1137.8 cw(c4579.53,1137.8) 4579.53,1148.8 cw(c4579.53,1137.8) 4590.53,1137.8 cw(c4579.53,1137.8)
  pour cut-out: 4548.03,1126.8 cw(c4548.03,1137.8) 4537.03,1137.8 cw(c4548.03,1137.8) 4548.03,1148.8 cw(c4548.03,1137.8) 4559.03,1137.8 cw(c4548.03,1137.8)
  pour cut-out: 4579.53,1221.28 cw(c4579.53,1232.28) 4568.53,1232.28 cw(c4579.53,1232.28) 4579.53,1243.28 cw(c4579.53,1232.28) 4590.53,1232.28 cw(c4579.53,1232.28)
  pour cut-out: 4473.75,1293.02 cw(c4473.75,1304.02) 4462.75,1304.02 cw(c4473.75,1304.02) 4473.75,1315.02 cw(c4473.75,1304.02) 4484.75,1304.02 cw(c4473.75,1304.02)
  pour cut-out: 4254.35,1153.67 cw(c4254.35,1164.67) 4243.35,1164.67 cw(c4254.35,1164.67) 4254.35,1175.67 cw(c4254.35,1164.67) 4265.35,1164.67 cw(c4254.35,1164.67)
  pour cut-out: 4199.68,938 cw(c4199.68,949) 4188.68,949 cw(c4199.68,949) 4199.68,960 cw(c4199.68,949) 4210.68,949 cw(c4199.68,949)
  pour cut-out: 4198.25,907.41 cw(c4198.25,918.41) 4187.25,918.41 cw(c4198.25,918.41) 4198.25,929.41 cw(c4198.25,918.41) 4209.25,918.41 cw(c4198.25,918.41)
  pour cut-out: 4297.33,744.22 cw(c4297.33,755.22) 4286.33,755.22 cw(c4297.33,755.22) 4297.33,766.22 cw(c4297.33,755.22) 4308.33,755.22 cw(c4297.33,755.22)
  pour cut-out: 4134.52,729.33 cw(c4134.52,740.33) 4123.52,740.33 cw(c4134.52,740.33) 4134.52,751.33 cw(c4134.52,740.33) 4145.52,740.33 cw(c4134.52,740.33)
  pour cut-out: 4054.52,729.33 cw(c4054.52,740.33) 4043.52,740.33 cw(c4054.52,740.33) 4054.52,751.33 cw(c4054.52,740.33) 4065.52,740.33 cw(c4054.52,740.33)
  pour cut-out: 3974.52,729.33 cw(c3974.52,740.33) 3963.52,740.33 cw(c3974.52,740.33) 3974.52,751.33 cw(c3974.52,740.33) 3985.52,740.33 cw(c3974.52,740.33)
  pour cut-out: 3894.52,729.33 cw(c3894.52,740.33) 3883.52,740.33 cw(c3894.52,740.33) 3894.52,751.33 cw(c3894.52,740.33) 3905.52,740.33 cw(c3894.52,740.33)
  pour cut-out: 3839.74,878.16 cw(c3839.74,889.16) 3828.74,889.16 cw(c3839.74,889.16) 3839.74,900.16 cw(c3839.74,889.16) 3850.74,889.16 cw(c3839.74,889.16)
  pour cut-out: 3840.65,880.56 cw(c3840.65,891.56) 3829.65,891.56 cw(c3840.65,891.56) 3840.65,902.56 cw(c3840.65,891.56) 3851.65,891.56 cw(c3840.65,891.56)
  pour cut-out: 3786.02,1094.07 cw(c3786.02,1105.07) 3775.02,1105.07 cw(c3786.02,1105.07) 3786.02,1116.07 cw(c3786.02,1105.07) 3797.02,1105.07 cw(c3786.02,1105.07)
  pour cut-out: 3618.06,1087.29 cw(c3618.06,1098.29) 3607.06,1098.29 cw(c3618.06,1098.29) 3618.06,1109.29 cw(c3618.06,1098.29) 3629.06,1098.29 cw(c3618.06,1098.29)
  pour cut-out: 3789.16,729.33 cw(c3789.16,740.33) 3778.16,740.33 cw(c3789.16,740.33) 3789.16,751.33 cw(c3789.16,740.33) 3800.16,740.33 cw(c3789.16,740.33)
  pour cut-out: 3741.26,665.25 cw(c3741.26,676.25) 3730.26,676.25 cw(c3741.26,676.25) 3741.26,687.25 cw(c3741.26,676.25) 3752.26,676.25 cw(c3741.26,676.25)
  pour cut-out: 3709.16,729.33 cw(c3709.16,740.33) 3698.16,740.33 cw(c3709.16,740.33) 3709.16,751.33 cw(c3709.16,740.33) 3720.16,740.33 cw(c3709.16,740.33)
  pour cut-out: 3270.48,959.63 cw(c3270.48,970.63) 3259.48,970.63 cw(c3270.48,970.63) 3270.48,981.63 cw(c3270.48,970.63) 3281.48,970.63 cw(c3270.48,970.63)
  pour cut-out: 2755,1182.28 cw(c2755,1193.28) 2744,1193.28 cw(c2755,1193.28) 2755,1204.28 cw(c2755,1193.28) 2766,1193.28 cw(c2755,1193.28)
  pour cut-out: 2755,1062.28 cw(c2755,1073.28) 2744,1073.28 cw(c2755,1073.28) 2755,1084.28 cw(c2755,1073.28) 2766,1073.28 cw(c2755,1073.28)
  pour cut-out: 782.67,830.46 cw(c782.67,841.46) 771.67,841.46 cw(c782.67,841.46) 782.67,852.46 cw(c782.67,841.46) 793.67,841.46 cw(c782.67,841.46)
  pour cut-out: 511.01,911.21 cw(c511.01,922.21) 500.01,922.21 cw(c511.01,922.21) 511.01,933.21 cw(c511.01,922.21) 522.01,922.21 cw(c511.01,922.21)
  pour cut-out: 487.01,911.21 cw(c487.01,922.21) 476.01,922.21 cw(c487.01,922.21) 487.01,933.21 cw(c487.01,922.21) 498.01,922.21 cw(c487.01,922.21)
  pour cut-out: 353.49,2033.8 cw(c353.49,2044.8) 342.49,2044.8 cw(c353.49,2044.8) 353.49,2055.8 cw(c353.49,2044.8) 364.49,2044.8 cw(c353.49,2044.8)
  pour cut-out: 1652.87,2416.2 cw(c1652.87,2427.2) 1641.87,2427.2 cw(c1652.87,2427.2) 1652.87,2438.2 cw(c1652.87,2427.2) 1663.87,2427.2 cw(c1652.87,2427.2)
  pour cut-out: 1633.62,2147.03 cw(c1633.62,2158.03) 1622.62,2158.03 cw(c1633.62,2158.03) 1633.62,2169.03 cw(c1633.62,2158.03) 1644.62,2158.03 cw(c1633.62,2158.03)
  pour cut-out: 1515,2110.52 cw(c1515,2121.52) 1504,2121.52 cw(c1515,2121.52) 1515,2132.52 cw(c1515,2121.52) 1526,2121.52 cw(c1515,2121.52)
  pour cut-out: 1329.38,2135.38 cw(c1329.38,2146.38) 1318.38,2146.38 cw(c1329.38,2146.38) 1329.38,2157.38 cw(c1329.38,2146.38) 1340.38,2146.38 cw(c1329.38,2146.38)
  pour cut-out: 1100.6,2014.75 cw(c1100.6,2025.75) 1089.6,2025.75 cw(c1100.6,2025.75) 1100.6,2036.75 cw(c1100.6,2025.75) 1111.6,2025.75 cw(c1100.6,2025.75)
  pour cut-out: 2068.7,1117.15 cw(c2068.7,1128.15) 2057.7,1128.15 cw(c2068.7,1128.15) 2068.7,1139.15 cw(c2068.7,1128.15) 2079.7,1128.15 cw(c2068.7,1128.15)
  pour cut-out: 1790.56,1264.75 cw(c1790.56,1275.75) 1779.56,1275.75 cw(c1790.56,1275.75) 1790.56,1286.75 cw(c1790.56,1275.75) 1801.56,1275.75 cw(c1790.56,1275.75)
  pour cut-out: 1852.79,1158.65 cw(c1852.79,1169.65) 1841.79,1169.65 cw(c1852.79,1169.65) 1852.79,1180.65 cw(c1852.79,1169.65) 1863.79,1169.65 cw(c1852.79,1169.65)
  pour cut-out: 1823.1,1158.65 cw(c1823.1,1169.65) 1812.1,1169.65 cw(c1823.1,1169.65) 1823.1,1180.65 cw(c1823.1,1169.65) 1834.1,1169.65 cw(c1823.1,1169.65)
  pour cut-out: 1431.18,909.24 cw(c1431.18,920.24) 1420.18,920.24 cw(c1431.18,920.24) 1431.18,931.24 cw(c1431.18,920.24) 1442.18,920.24 cw(c1431.18,920.24)
  pour cut-out: 1907.08,680.8 cw(c1907.08,691.8) 1896.08,691.8 cw(c1907.08,691.8) 1907.08,702.8 cw(c1907.08,691.8) 1918.08,691.8 cw(c1907.08,691.8)
  pour cut-out: 1860.84,557 cw(c1860.84,568) 1849.84,568 cw(c1860.84,568) 1860.84,579 cw(c1860.84,568) 1871.84,568 cw(c1860.84,568)
  pour cut-out: 2289.91,559.09 cw(c2289.91,570.09) 2278.91,570.09 cw(c2289.91,570.09) 2289.91,581.09 cw(c2289.91,570.09) 2300.91,570.09 cw(c2289.91,570.09)
  pour cut-out: 5203.54,2383.54 ccw(c5203.54,2440.21) 5260.21,2440.21 ccw(c5203.54,2440.21) 5203.54,2496.87 ccw(c5203.54,2440.21) 5146.88,2440.21 ccw(c5203.54,2440.21)
  pour cut-out: 5061.12,2486.78 cw(c5061.12,2497.78) 5050.12,2497.78 cw(c5061.12,2497.78) 5061.12,2508.78 cw(c5061.12,2497.78) 5072.12,2497.78 cw(c5061.12,2497.78)
  pour cut-out: 4832,2074 4832,2059.66 4844.48,2047.18 4925.98,2047.18 4925.98,2073.95 4921.48,2078.46
  pour cut-out: 5038,2033 5041.62,2036.62 5041.62,2070.73 5023.8,2070.73 5009.57,2056.5 5023.06,2043.02 5023.06,2025.17
  pour cut-out: 2348,2147 2348.1,2147.1 2348.1,2165.96 2336.32,2165.96 2335.64,2166.63 2332.63,2163.62 2332.63,2145.26
  pour cut-out: 3060,957 3060,922.36 3071.15,911.21 3337.67,911.21 3337.67,918.99 3276.71,979.96 3266.29,969.54 3039.76,969.54
  pour cut-out: 4242.29,605.71 4273.29,574.71 4330.29,631.71 4299.29,662.71
  pour cut-out: 4313,535 4344,504 4401,561 4370,592
  pour cut-out: 4224.47,446.47 4255.47,415.47 4312.47,472.47 4281.47,503.47
  text ".Layer_Name" at 575,-860 h60
L16 GND:
  pour cut-out: 4313,535 4344,504 4401,561 4370,592
  pour cut-out: 4242.29,605.71 4273.29,574.71 4330.29,631.71 4299.29,662.71
  pour cut-out: 4224.47,446.47 4255.47,415.47 4312.47,472.47 4281.47,503.47
  text ".Layer_Name" at 575,-860 h60
L14 PWR:
  text ".Layer_Name" at 575,-860 h60
L5 PWR/SIG:
  pour cut-out: 1832.62,2564.41 cw(c1832.62,2586.06) 1810.97,2586.06 cw(c1832.62,2586.06) 1832.62,2607.71 cw(c1832.62,2586.06) 1854.27,2586.06 cw(c1832.62,2586.06)
  pour cut-out: 1652.87,2416.2 cw(c1652.87,2427.2) 1641.87,2427.2 cw(c1652.87,2427.2) 1652.87,2438.2 cw(c1652.87,2427.2) 1663.87,2427.2 cw(c1652.87,2427.2)
  pour cut-out: 1515,2110.52 cw(c1515,2121.52) 1504,2121.52 cw(c1515,2121.52) 1515,2132.52 cw(c1515,2121.52) 1526,2121.52 cw(c1515,2121.52)
  text ".Layer_Name" at 575.58,-858.07 h60
L6 GND:
  text ".Layer_Name" at 575,-860 h60
L7 SIGNAL:
  pour cut-out: 5129.79,762.05 cw(c5129.79,773.05) 5118.79,773.05 cw(c5129.79,773.05) 5129.79,784.05 cw(c5129.79,773.05) 5140.79,773.05 cw(c5129.79,773.05)
  pour cut-out: 5037.22,1704.16 cw(c5037.22,1715.16) 5026.22,1715.16 cw(c5037.22,1715.16) 5037.22,1726.16 cw(c5037.22,1715.16) 5048.22,1715.16 cw(c5037.22,1715.16)
  pour cut-out: 4972.22,1704.16 cw(c4972.22,1715.16) 4961.22,1715.16 cw(c4972.22,1715.16) 4972.22,1726.16 cw(c4972.22,1715.16) 4983.22,1715.16 cw(c4972.22,1715.16)
  pour cut-out: 4966.23,1665 cw(c4966.23,1676) 4955.23,1676 cw(c4966.23,1676) 4966.23,1687 cw(c4966.23,1676) 4977.23,1676 cw(c4966.23,1676)
  pour cut-out: 5084,811 5106.13,833.13 5113.97,833.13 5113.97,830.3 5119.62,824.66 5099.55,804.59 5094.84,804.59
  pour cut-out: 4926.29,1000.97 4926.29,1018.84 4924,1021.13 4919.82,1016.96 4903.87,1016.96 4903.87,1003.08 4901.76,1000.97
  pour cut-out: 5639,770 5639,789.69 5635.96,792.73 5632.38,792.73
  pour cut-out: 4806,1058 4810,1054 4810,1022.88 4841.55,1022.88 4843.18,1021.25 4853.18,1031.25 4853.18,1042.37 4833.49,1062.07 4830.11,1058.69 4810,1058.69
  pour cut-out: 4892,1036 4886.01,1030.01 4886.01,1007.04 4895.69,1007.04 4901.76,1000.97 4918.05,1017.26 4924,1017.26 4924,1021.13 4907.52,1037.61
  pour cut-out: 4968,1903 4968,1926 4972,1930 4996,1930 4996,1909 4999,1906 4990,1897 4975,1897 4970,1902
  pour cut-out: 5022.81,1600.38 5034.12,1589.06 5034.12,1563.71 5026.14,1555.72 5019.61,1562.24 5019.3,1562.24
  text ".Layer_Name" at 575,-860 h60
L8 GND:
  text ".Layer_Name" at 575,-860 h60
L9 GND:
  text ".Layer_Name" at 575,-860 h60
